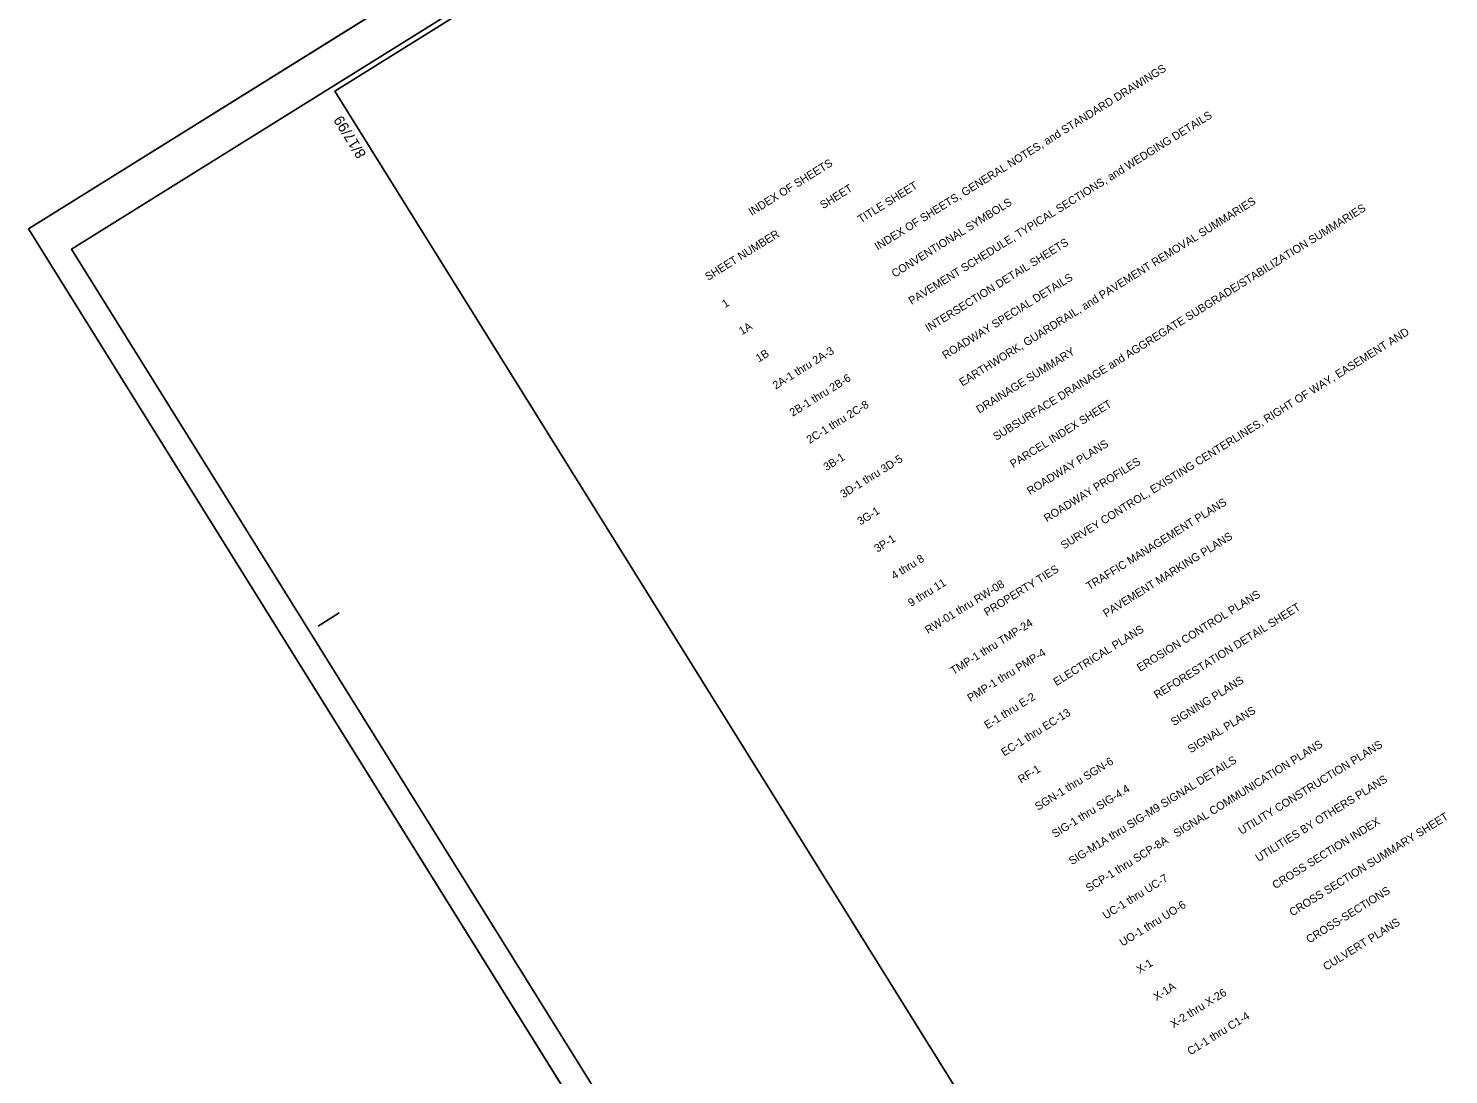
# Model space of a CAD drawing. Extents: x 2047559 to 2049567, y 759970 to 761789.
# Drawn here: x 2047559 to 2048269, y 760477 to 760999 of the extents above; entities that cross this region are included whole.
import ezdxf

# ---------------------------------------------------------------- set-up
doc = ezdxf.new("R2010")
doc.units = 0
for name, color, linetype in [('Sheet Cutting Line CELL', 7, 'Continuous'), ('Sheet Data Text CELL', 7, 'Continuous'), ('Sheet Plan CELL', 7, 'Continuous'), ('Sheet Plot Border Inside CELL', 7, 'Continuous'), ('Sheet Plot Border Outside CELL', 7, 'Continuous')]:
    doc.layers.add(name, color=color, linetype=linetype)

msp = doc.modelspace()

# ---------------------------------------------------------------- linework, layer by layer
at = {"layer": 'Sheet Cutting Line CELL'}
for p, q in [((2048987.97, 761789.33), (2047559, 760899.25)), ((2047559, 760899.25), (2048137.94, 759969.81))]:
    msp.add_line(p, q, dxfattribs=at)
at = {"layer": 'Sheet Plan CELL'}
for p, q in [((2047712.23, 760968.18), (2047712.23, 760968.18)), ((2047703.82, 760700.81), (2047714.43, 760707.42))]:
    msp.add_line(p, q, dxfattribs=at)
msp.add_lwpolyline([(2048985.43, 761761.24), (2047712.23, 760968.18), (2048267.37, 760076.94), (2049540.57, 760870)], close=True, dxfattribs=at)
at = {"layer": 'Sheet Plot Border Inside CELL'}
msp.add_lwpolyline([(2048138.4, 759993.66), (2049552.51, 760874.48), (2048994.72, 761769.97), (2047580.61, 760889.15)], close=True, dxfattribs=at)
at = {"layer": 'Sheet Plot Border Outside CELL'}
msp.add_lwpolyline([(2048137.94, 759969.81), (2049566.9, 760859.89), (2048987.97, 761789.33), (2047559, 760899.25)], close=True, dxfattribs=at)

# ---------------------------------------------------------------- texts
at = {"layer": 'Sheet Data Text CELL'}
for s, p in [('INDEX OF SHEETS, GENERAL NOTES, and STANDARD DRAWINGS', (2047983.6, 760888.38)), ('PAVEMENT SCHEDULE, TYPICAL SECTIONS, and WEDGING DETAILS', (2048000.52, 760861.22)), ('                        INDEX OF SHEETS ', (2047890.32, 760886.82)), ('SHEET NUMBER                 SHEET   ', (2047898.78, 760873.24)), ('TITLE SHEET', (2047975.14, 760901.96)), ('CONVENTIONAL SYMBOLS', (2047992.06, 760874.8)), ('EARTHWORK, GUARDRAIL, and PAVEMENT REMOVAL SUMMARIES', (2048025.9, 760820.47)), ('SUBSURFACE DRAINAGE and AGGREGATE SUBGRADE/STABILIZATION SUMMARIES', (2048042.81, 760793.31)), ('INTERSECTION DETAIL SHEETS', (2048008.98, 760847.63)), ('ROADWAY SPECIAL DETAILS', (2048017.44, 760834.05)), ('1', (2047907.24, 760859.66)), ('1A', (2047915.7, 760846.08)), ('SURVEY CONTROL, EXISTING CENTERLINES, RIGHT OF WAY, EASEMENT AND ', (2048076.65, 760738.99)), ('2A-1 thru 2A-3', (2047932.61, 760818.92)), ('DRAINAGE SUMMARY', (2048034.36, 760806.89)), ('1B', (2047924.15, 760832.5)), ('2B-1 thru 2B-6', (2047941.07, 760805.34)), ('2C-1 thru 2C-8', (2047949.53, 760791.76)), ('PARCEL INDEX SHEET', (2048051.27, 760779.73)), ('ROADWAY PLANS', (2048059.73, 760766.15)), ('3B-1', (2047957.99, 760778.18)), ('3D-1 thru 3D-5', (2047966.45, 760764.6)), ('ROADWAY PROFILES', (2048068.19, 760752.57)), ('TRAFFIC MANAGEMENT PLANS', (2048089.34, 760718.62)), ('3G-1', (2047974.91, 760751.02)), ('3P-1', (2047983.37, 760737.43)), ('PAVEMENT MARKING PLANS', (2048097.8, 760705.04)), ('4 thru 8', (2047991.83, 760723.85)), ('                    PROPERTY TIES', (2048012.98, 760689.9)), ('9 thru 11', (2048000.29, 760710.27)), ('RW-01 thru RW-08', (2048008.75, 760696.69)), ('EROSION CONTROL PLANS', (2048114.72, 760677.87)), ('REFORESTATION DETAIL SHEET', (2048123.18, 760664.29)), ('TMP-1 thru TMP-24', (2048021.44, 760676.32)), ('E-1 thru E-2        ELECTRICAL PLANS', (2048038.35, 760649.16)), ('PMP-1 thru PMP-4', (2048029.9, 760662.74)), ('SIGNING PLANS', (2048131.64, 760650.71)), ('EC-1 thru EC-13', (2048046.81, 760635.58)), ('SIGNAL PLANS', (2048140.1, 760637.13)), ('SCP-1 thru SCP-8A   SIGNAL COMMUNICATION PLANS', (2048089.11, 760567.67)), ('UTILITY CONSTRUCTION PLANS', (2048165.47, 760596.39)), ('SGN-1 thru SGN-6', (2048063.73, 760608.42)), ('SIG-M1A thru SIG-M9 SIGNAL DETAILS', (2048080.65, 760581.25)), ('RF-1', (2048055.27, 760622)), ('SIG-1 thru SIG-4.4', (2048072.19, 760594.84)), ('UTILITIES BY OTHERS PLANS', (2048173.93, 760582.81)), ('CROSS SECTION SUMMARY SHEET', (2048190.85, 760555.65)), ('CROSS SECTION INDEX', (2048182.39, 760569.23)), ('UC-1 thru UC-7', (2048097.57, 760554.09)), ('CROSS-SECTIONS', (2048199.31, 760542.07)), ('UO-1 thru UO-6', (2048106.03, 760540.51)), ('CULVERT PLANS', (2048207.77, 760528.48)), ('X-1', (2048114.49, 760526.93)), ('X-1A', (2048122.95, 760513.35)), ('X-2 thru X-26', (2048131.41, 760499.77)), ('C1-1 thru C1-4', (2048139.87, 760486.19))]:
    msp.add_text(s, height=4, rotation=31.91803, dxfattribs=at).set_placement(p)
at = {"layer": 'Sheet Plan CELL'}
msp.add_text('8/17/99', height=5.25, rotation=121.91803, dxfattribs=at).set_placement((2047728.08, 760936.59))

doc.saveas('drawing.dxf')
